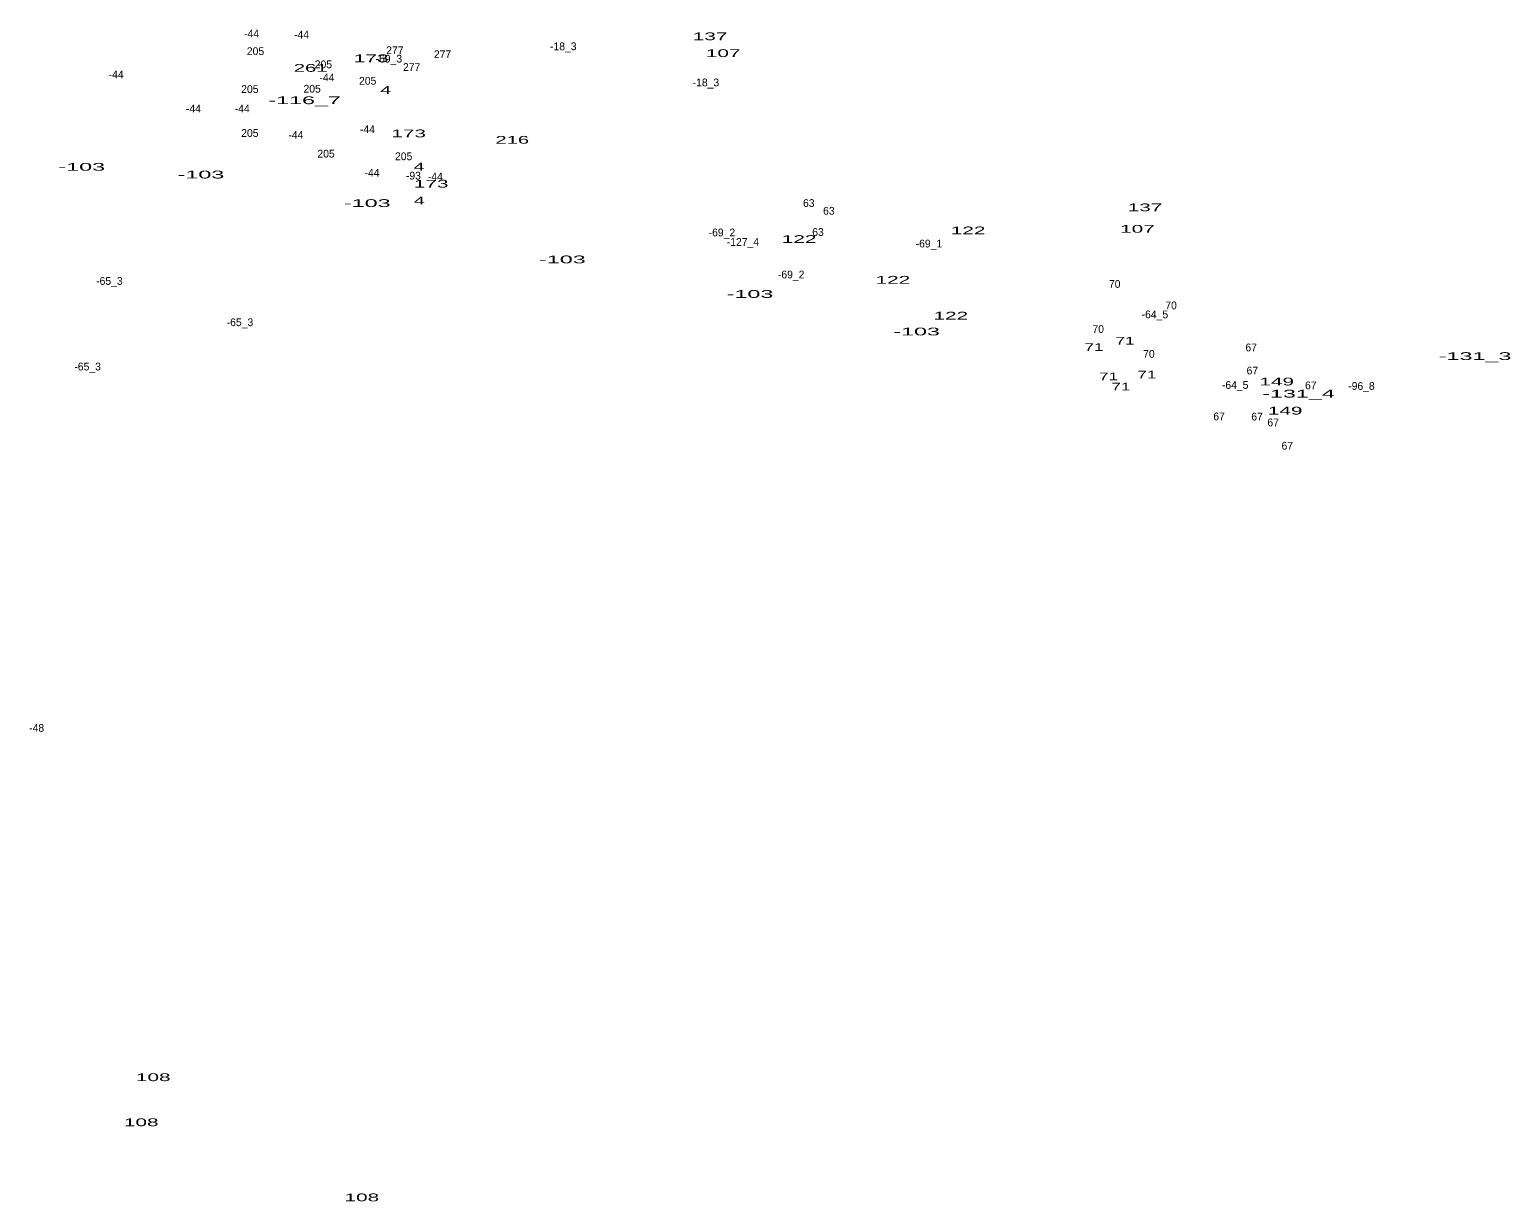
# Model space of a CAD drawing. Extents: x -656096 to -652763, y -1002270 to -998958.
# Drawn here: x -653527 to -652763, y -1002270 to -1001666 of the extents above; entities that cross this region are included whole.
import ezdxf
from ezdxf.enums import TextEntityAlignment as Align

# ---------------------------------------------------------------- set-up
doc = ezdxf.new("R2010")
doc.units = 0
doc.header["$LTSCALE"] = 1.6
doc.layers.add('24', color=7, linetype='Continuous')

msp = doc.modelspace()

# ---------------------------------------------------------------- texts
at = {"layer": '24'}
for s, p in [('-44', (-653412.813, -1001669.56)), ('-44', (-653387.053, -1001670.14)), ('-18_3', (-653251.986, -1001676.18)), ('205', (-653410.821, -1001678.68)), ('-69_3', (-653341.993, -1001682.55)), ('277', (-653338.899, -1001678.2)), ('277', (-653314.309, -1001680.28)), ('-44', (-653482.713, -1001690.68)), ('205', (-653375.771, -1001685.46)), ('277', (-653330.229, -1001686.87)), ('205', (-653413.721, -1001698.24)), ('205', (-653381.581, -1001698.05)), ('-44', (-653373.933, -1001692.21)), ('205', (-653352.921, -1001693.98)), ('-18_3', (-653178.386, -1001694.8)), ('-44', (-653442.823, -1001708.3)), ('-44', (-653417.653, -1001708.3)), ('205', (-653413.721, -1001720.91)), ('-44', (-653389.963, -1001721.86)), ('-44', (-653353.013, -1001718.94)), ('205', (-653374.411, -1001731.56)), ('205', (-653334.341, -1001732.92)), ('-44', (-653350.693, -1001741.41)), ('-93', (-653329.34, -1001742.9)), ('-44', (-653317.973, -1001743.34)), ('63', (-653125.293, -1001757.05)), ('63', (-653114.923, -1001761.02)), ('-69_2', (-653170.113, -1001772.2)), ('63', (-653120.543, -1001771.98)), ('-127_4', (-653159.286, -1001777.11)), ('-69_1', (-653063.297, -1001777.94)), ('-65_3', (-653486.208, -1001797.22)), ('-69_2', (-653134.393, -1001793.89)), ('70', (-652967.417, -1001798.78)), ('70', (-652938.337, -1001809.83)), ('-65_3', (-653418.828, -1001818.53)), ('-64_5', (-652946.702, -1001814.47)), ('70', (-652975.947, -1001822.05)), ('70', (-652949.777, -1001834.85)), ('67', (-652896.978, -1001831.52)), ('-65_3', (-653497.438, -1001841.38)), ('67', (-652896.398, -1001843.44)), ('-64_5', (-652905.262, -1001850.89)), ('67', (-652866.248, -1001851.1)), ('-96_8', (-652840.093, -1001851.41)), ('67', (-652913.558, -1001867.1)), ('67', (-652893.978, -1001867.2)), ('67', (-652885.638, -1001870.21)), ('67', (-652878.368, -1001882.23)), ('-48', (-653523.749, -1002027.81))]:
    msp.add_text(s, height=4, dxfattribs=at).set_placement(p, align=Align.CENTER)
for s, width, p in [('137', 2, (-653176.233, -1001671.02)), ('173', 2, (-653351.143, -1001682.36)), ('107', 2, (-653169.479, -1001679.69)), ('261', 1.95, (-653382.343, -1001687.31)), ('4', 1.9, (-653343.667, -1001698.71)), ('-116_7', 2.25, (-653385.467, -1001704)), ('173', 2, (-653331.773, -1001721.1)), ('216', 1.95, (-653278.313, -1001724.41)), ('-103', 2.25, (-653500.467, -1001738.34)), ('-103', 2.25, (-653438.957, -1001742.34)), ('4', 1.9, (-653326.417, -1001738.27)), ('173', 2, (-653320.163, -1001747.06)), ('-103', 2.25, (-653353.137, -1001757.07)), ('4', 1.9, (-653326.227, -1001755.73)), ('137', 2, (-652951.813, -1001759.26)), ('122', 2, (-653130.287, -1001775.61)), ('122', 2, (-653043.087, -1001771.16)), ('107', 2, (-652955.699, -1001770.34)), ('-103', 2.25, (-653252.447, -1001786.12)), ('122', 2, (-653081.877, -1001796.63)), ('-103', 2.25, (-653155.627, -1001803.94)), ('122', 2, (-653051.997, -1001815.13)), ('-103', 2.25, (-653069.657, -1001823.31)), ('71', 1.65, (-652962.073, -1001828.06)), ('71', 1.65, (-652978.173, -1001831.36)), ('-131_3', 2.25, (-652781.457, -1001836)), ('71', 1.65, (-652970.603, -1001846.48)), ('71', 1.65, (-652964.213, -1001851.72)), ('71', 1.65, (-652950.833, -1001845.52)), ('149', 2, (-652883.828, -1001849.12)), ('-131_4', 2.25, (-652872.593, -1001855.37)), ('149', 2, (-652879.478, -1001864.13)), ('108', 2, (-653463.584, -1002208.03)), ('108', 2, (-653469.784, -1002231.28)), ('108', 2, (-653355.924, -1002270.02))]:
    msp.add_text(s, height=4, dxfattribs=dict(at, width=width)).set_placement(p, align=Align.CENTER)

doc.saveas('drawing.dxf')
